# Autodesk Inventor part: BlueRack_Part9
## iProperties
Shininess: 64.0
Length Units: 11272
Angle Units: 11279
Time Units: 11290
Mass Units: 11286
Length Display Precision: 3
Angle Display Precision: 2
Compacted: True
Part Number: BlueRack_Part9
Document SubType Name: Modeling
Created: 2004-12
Designer: John Blackburn
Material: Steel, Mild
Manufacturer: Standard
Standards Organization: Custom
Density: 0.0
Volumn: 0.0
Area: 0.0
PropertySet Name: Model Information
Control State: 0
Master: False
Checked Out: False
Author: John Blackburn
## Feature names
1. Extrusion1
